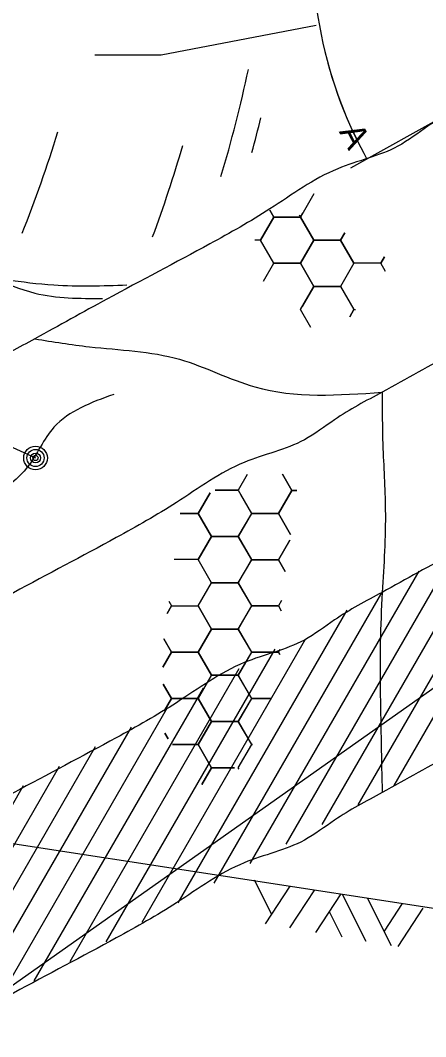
# Model space of a CAD drawing. Extents: x 3 to 3592, y -602 to 1171.
# Drawn here: x 3315.3 to 3353.3, y -164 to -68.8 of the extents above; entities that cross this region are included whole.
import ezdxf

# ---------------------------------------------------------------- set-up
doc = ezdxf.new("R2010")
doc.units = 0
doc.layers.add('1', color=7, linetype='Continuous')
doc.layers.add('2', color=7, linetype='Continuous')

msp = doc.modelspace()

# ---------------------------------------------------------------- linework, layer by layer
at = {"layer": '1'}
msp.add_line((2687.879, -601.809), (3528.879, -7.809), dxfattribs=at)
at = {"layer": '2'}
for p, q in [((3328.499, -72.022), (3343.015, -69.239)), ((3322.279, -72.022), (3328.499, -72.022)), ((3356.405, -76.98), (3346.233, -82.639)), ((3296.89, -100.672), (3316.735, -109.792)), ((3350.293, -140.456), (3366.097, -113.083)), ((3346.925, -142.288), (3362.732, -114.91)), ((3343.557, -144.12), (3359.367, -116.736)), ((3340.188, -145.952), (3356.002, -118.563)), ((3336.82, -147.785), (3352.636, -120.389)), ((3333.451, -149.617), (3349.271, -122.216)), ((3330.083, -151.449), (3345.906, -124.042)), ((3326.715, -153.281), (3342.02, -126.772)), ((3323.346, -155.114), (3339.176, -127.695)), ((3319.978, -156.946), (3335.811, -129.522)), ((3316.609, -158.778), (3332.446, -131.348)), ((3313.241, -160.61), (3329.081, -133.175)), ((3309.872, -162.443), (3325.716, -135.001)), ((3307.936, -161.795), (3322.351, -136.828)), ((3307.863, -157.919), (3318.986, -138.654)), ((3307.821, -153.989), (3315.621, -140.481)), ((3307.934, -144.88), (3363.528, -153.432)), ((3337.205, -149.314), (3338.827, -152.532)), ((3340.554, -149.898), (3338.248, -153.415)), ((3342.842, -150.25), (3340.51, -153.806)), ((3345.303, -150.628), (3342.942, -154.228)), ((3345.432, -150.648), (3347.646, -155.042)), ((3347.823, -151.061), (3350.038, -155.456)), ((3344.218, -152.282), (3345.414, -154.655)), ((3351.07, -151.515), (3349.364, -154.118)), ((3353.006, -151.954), (3350.641, -155.56))]:
    msp.add_line(p, q, dxfattribs=at)
for points in [[(3342.791, -85.059), (3341.541, -87.224)], [(3338.668, -86.577), (3339.041, -87.224)], [(3339.041, -87.224), (3338.668, -86.577)], [(3339.041, -87.224), (3337.791, -89.389)], [(3341.541, -87.224), (3339.041, -87.224)], [(3341.419, -87.003), (3341.546, -87.223)], [(3341.546, -87.223), (3341.758, -86.855)], [(3342.796, -89.388), (3341.546, -87.223)], [(3337.791, -89.389), (3337.262, -89.389)], [(3345.296, -89.388), (3342.796, -89.388)], [(3345.696, -88.694), (3345.296, -89.388)], [(3345.296, -89.388), (3345.696, -88.694)], [(3346.546, -91.553), (3345.296, -89.388)], [(3349.389, -90.958), (3349.046, -91.553)], [(3349.046, -91.553), (3349.389, -90.958)], [(3338.065, -93.245), (3339.041, -91.554)], [(3339.041, -91.554), (3341.541, -91.554)], [(3341.541, -91.554), (3342.791, -93.719)], [(3349.046, -91.553), (3346.546, -91.553)], [(3349.483, -92.311), (3349.046, -91.553)], [(3341.546, -95.883), (3342.796, -93.718)], [(3342.791, -93.719), (3341.709, -95.594)], [(3342.796, -93.718), (3345.296, -93.718)], [(3345.296, -93.718), (3346.546, -95.883)], [(3342.516, -97.562), (3341.546, -95.883)], [(3346.546, -95.883), (3346.146, -96.575)], [(3346.146, -96.575), (3346.546, -95.883)], [(3346.546, -95.883), (3346.688, -95.883)], [(3336.56, -111.344), (3335.708, -112.82)], [(3340.721, -112.826), (3339.841, -111.303)], [(3339.841, -111.303), (3340.721, -112.826)], [(3333.075, -113.051), (3331.958, -114.985)], [(3331.958, -114.985), (3333.075, -113.051)], [(3333.548, -112.82), (3335.708, -112.82)], [(3335.708, -112.82), (3333.548, -112.82)], [(3335.708, -112.82), (3336.958, -114.985)], [(3336.971, -114.991), (3335.944, -113.212)], [(3340.721, -112.826), (3339.471, -114.991)], [(3339.471, -114.991), (3340.721, -112.826)], [(3341.21, -112.826), (3340.721, -112.826)], [(3340.721, -112.826), (3341.21, -112.826)], [(3330.285, -114.985), (3331.958, -114.985)], [(3331.958, -114.985), (3330.285, -114.985)], [(3331.958, -114.985), (3333.208, -117.15)], [(3333.208, -117.15), (3331.958, -114.985)], [(3336.958, -114.985), (3335.708, -117.15)], [(3335.721, -117.156), (3336.971, -114.991)], [(3339.471, -114.991), (3336.971, -114.991)], [(3336.971, -114.991), (3339.471, -114.991)], [(3340.607, -116.959), (3339.471, -114.991)], [(3339.471, -114.991), (3340.607, -116.959)], [(3333.208, -117.15), (3331.958, -119.315)], [(3335.708, -117.15), (3333.208, -117.15)], [(3336.971, -119.321), (3335.721, -117.156)], [(3340.53, -117.488), (3339.471, -119.321)], [(3339.471, -119.321), (3340.53, -117.488)], [(3331.958, -119.315), (3329.713, -119.315)], [(3335.721, -121.486), (3336.971, -119.321)], [(3339.471, -119.321), (3336.971, -119.321)], [(3336.971, -119.321), (3339.471, -119.321)], [(3340.103, -120.416), (3339.471, -119.321)], [(3339.471, -119.321), (3340.103, -120.416)], [(3336.971, -123.651), (3335.721, -121.486)], [(3329.458, -123.645), (3329.047, -124.358)], [(3329.047, -124.358), (3329.458, -123.645)], [(3329.2, -123.197), (3329.458, -123.645)], [(3329.458, -123.645), (3331.958, -123.645)], [(3331.958, -123.645), (3333.208, -125.81)], [(3335.721, -125.816), (3336.971, -123.651)], [(3336.971, -123.651), (3339.471, -123.651)], [(3339.471, -123.651), (3336.971, -123.651)], [(3339.762, -123.148), (3339.471, -123.651)], [(3339.471, -123.651), (3339.73, -124.1)], [(3333.208, -125.81), (3331.958, -127.975)], [(3336.971, -127.981), (3335.721, -125.816)], [(3328.735, -126.721), (3329.458, -127.975)], [(3329.458, -127.975), (3328.735, -126.721)], [(3329.458, -127.975), (3328.64, -129.392)], [(3328.64, -129.392), (3329.458, -127.975)], [(3329.458, -127.975), (3331.958, -127.975)], [(3331.958, -127.975), (3329.458, -127.975)], [(3331.958, -127.975), (3333.208, -130.14)], [(3335.721, -130.146), (3336.971, -127.981)], [(3339.471, -127.981), (3336.971, -127.981)], [(3336.971, -127.981), (3339.471, -127.981)], [(3339.609, -127.743), (3339.471, -127.981)], [(3339.471, -127.981), (3339.609, -127.743)], [(3339.594, -128.194), (3339.471, -127.981)], [(3339.471, -127.981), (3339.594, -128.194)], [(3333.208, -130.14), (3331.958, -132.305)], [(3336.971, -132.311), (3335.721, -130.146)], [(3328.691, -130.976), (3329.458, -132.305)], [(3329.458, -132.305), (3328.691, -130.976)], [(3329.458, -132.305), (3328.773, -133.492)], [(3328.773, -133.492), (3329.458, -132.305)], [(3329.458, -132.305), (3331.958, -132.305)], [(3331.958, -132.305), (3329.458, -132.305)], [(3331.958, -132.305), (3333.208, -134.47)], [(3335.721, -134.476), (3336.971, -132.311)], [(3338.726, -132.311), (3336.971, -132.311)], [(3336.971, -132.311), (3338.726, -132.311)], [(3333.208, -134.47), (3331.958, -136.635)], [(3331.958, -136.635), (3333.208, -134.47)], [(3333.208, -134.47), (3335.708, -134.47)], [(3335.708, -134.47), (3336.958, -136.635)], [(3336.971, -136.641), (3335.721, -134.476)], [(3328.839, -135.562), (3329.14, -136.083)], [(3329.14, -136.083), (3328.839, -135.562)], [(3329.548, -136.635), (3331.958, -136.635)], [(3331.958, -136.635), (3329.548, -136.635)], [(3331.958, -136.635), (3333.208, -138.8)], [(3333.208, -138.8), (3331.958, -136.635)], [(3335.721, -138.806), (3336.971, -136.641)], [(3336.958, -136.635), (3336.505, -137.419)], [(3337.05, -136.641), (3336.971, -136.641)], [(3336.971, -136.641), (3337.05, -136.641)], [(3333.208, -138.8), (3332.305, -140.365)], [(3332.305, -140.365), (3333.208, -138.8)], [(3333.208, -138.8), (3335.376, -138.8)], [(3335.376, -138.8), (3333.208, -138.8)], [(3335.799, -138.942), (3335.721, -138.806)]]:
    msp.add_lwpolyline(points, dxfattribs=at)
for points in [[(3337.791, -89.389), (3339.041, -87.224), (3341.541, -87.224), (3342.791, -89.389), (3341.541, -91.554), (3339.041, -91.554)], [(3341.546, -91.553), (3342.796, -89.388), (3345.296, -89.388), (3346.546, -91.553), (3345.296, -93.718), (3342.796, -93.718)], [(3331.958, -119.315), (3333.208, -117.15), (3335.708, -117.15), (3336.958, -119.315), (3335.708, -121.48), (3333.208, -121.48)], [(3331.958, -123.645), (3333.208, -121.48), (3335.708, -121.48), (3336.958, -123.645), (3335.708, -125.81), (3333.208, -125.81)], [(3331.958, -127.975), (3333.208, -125.81), (3335.708, -125.81), (3336.958, -127.975), (3335.708, -130.14), (3333.208, -130.14)], [(3331.958, -132.305), (3333.208, -130.14), (3335.708, -130.14), (3336.958, -132.305), (3335.708, -134.47), (3333.208, -134.47)]]:
    msp.add_lwpolyline(points, close=True, dxfattribs=at)
for radius in [1.107, 0.804, 0.464, 0.239]:
    msp.add_circle((3316.735, -109.792), radius, dxfattribs=at)
for centre, radius, start, end in [((3383.024, -62.172), 40.352, 171.25513, 209.08787), ((3383.023, -62.172), 40.351, 195.26554, 209.08823), ((3221.758, -49.306), 117.398, 343.10984, 348.16172), ((3223.786, -50.067), 117.398, 344.63962, 346.26216), ((3206.541, -44.995), 117.398, 338.11936, 343.03778), ((3217.7, -48.038), 117.398, 339.54634, 343.94189)]:
    msp.add_arc(centre, radius, start, end, dxfattribs=at)
for points in [[(3357.934, -76.13), (3353.473, -78.713), (3350.655, -80.591), (3345.02, -82.704), (3338.68, -86.461), (3333.045, -89.748), (3323.418, -94.914), (3316.684, -98.63)], [(3261.637, -78.62), (3266.455, -80.141), (3272.035, -81.917), (3278.628, -83.946), (3286.237, -86.482), (3293.845, -88.764), (3300.185, -90.539), (3309.569, -92.315), (3318.445, -93.583), (3325.292, -93.583)], [(3260.115, -79.127), (3262.398, -80.141), (3266.202, -80.395), (3270.006, -81.917), (3273.049, -83.438), (3276.6, -84.96), (3282.94, -86.735), (3289.787, -88.764), (3295.367, -90.539), (3303.482, -92.568), (3306.272, -92.568), (3312.612, -93.075), (3316.67, -94.343), (3323.01, -94.851)], [(3390.434, -81.13), (3385.973, -83.713), (3383.155, -85.591), (3377.52, -87.704), (3371.18, -91.461), (3365.545, -94.748), (3355.918, -99.914), (3349.184, -103.63)], [(3316.684, -98.63), (3312.223, -101.213), (3309.405, -103.091), (3303.77, -105.204), (3297.43, -108.961), (3291.795, -112.248), (3282.168, -117.414), (3275.434, -121.13)], [(3316.684, -98.63), (3321.774, -99.375), (3330.227, -100.549), (3337.271, -103.132), (3349.184, -103.63)], [(3390.434, -99.88), (3385.973, -102.463), (3383.155, -104.341), (3377.52, -106.454), (3371.18, -110.211), (3365.545, -113.498), (3355.918, -118.664), (3349.184, -122.38)], [(3349.184, -103.63), (3344.723, -106.213), (3341.905, -108.091), (3336.27, -110.204), (3329.93, -113.961), (3324.295, -117.248), (3314.668, -122.414), (3307.934, -126.13)], [(3349.184, -103.63), (3349.246, -108.533), (3349.481, -114.637), (3349.184, -122.38)], [(3324.058, -103.835), (3318.461, -106.916), (3315.993, -110.619), (3308.747, -115.163)], [(3390.434, -118.63), (3385.973, -121.213), (3383.155, -123.091), (3377.52, -125.204), (3371.18, -128.961), (3365.545, -132.248), (3355.918, -137.414), (3349.184, -141.13)], [(3349.184, -122.38), (3344.723, -124.963), (3341.905, -126.841), (3336.27, -128.954), (3329.93, -132.711), (3324.295, -135.998), (3314.668, -141.164), (3307.934, -144.88)], [(3349.184, -122.38), (3349.012, -127.082), (3349.012, -132.013), (3349.184, -141.13)], [(3349.184, -141.13), (3344.723, -143.713), (3341.905, -145.591), (3336.27, -147.704), (3329.93, -151.461), (3324.295, -154.748), (3314.668, -159.914), (3307.934, -163.63)]]:
    msp.add_spline(points, degree=3, dxfattribs=at)

# ---------------------------------------------------------------- texts
msp.add_text('A', height=2.333, rotation=297.43142, dxfattribs=at).set_placement((3345.114, -79.22))

doc.saveas('drawing.dxf')
